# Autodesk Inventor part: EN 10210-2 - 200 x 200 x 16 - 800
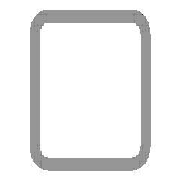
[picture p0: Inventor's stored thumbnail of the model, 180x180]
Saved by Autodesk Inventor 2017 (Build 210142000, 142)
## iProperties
IsCustomPart: 1
Created: 2017-11
Part Number: EN 10210-2 - 200 x 200 x 16 - 800
Material: Steel, Mild
Description: Tube
Document SubType Name: Modeling
Standard: DIN
Designer: iusti
Standard Revision: 2006-07
Standards Organization: DIN
Language: en-US
Size Designation: 200 x 200 x 16
Categories: <MemberInstance><Categories><Category DisplayName="Structural Shapes" InternalName="089c4875-fa83-4c05-b084-43b9cc11f5ed" Mnemonic="GRDR"><CategoryParameter Dis
Stock Number: 200 x 200 x 16
Density: 7.85 g/cm^3
Appearance: Semi-Polished
Mass: 72228.2 g
Surface Area: 11456.6 cm^2
Volume: 9201.05 cm^3
_CCFamilyMember: 94
_CCFamilyDisplayName: DIN EN 10210-2 (Square) - Tube — Sizes in parentheses have been withdrawn
_FrameMemberDoc: Frame Member File
_Version: 15.0.0
_GetPNFromCC: 1
G_L: 800.000 mm
G_W: 200.000 mm
G_H: 200.000 mm
+E8E52DC3-696E-4D1F-9B18-A30D357A272B+CUTDETAIL1: Cut
+4C075105-3F5C-41BE-BEAB-D27544A0B937+CUTDETAIL2: Cut
Author: iusti
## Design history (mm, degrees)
node "Start plane"
node "End plane"
sketch "Sketch"
  geometry: L1 (-100, -76)-(-100, 76); L2 (-76, 100)-(76, 100); L3 (100, 76)-(100, -76); L4 (76, -100)-(-76, -100); L5 (-68, 84)-(68, 84); L6 (84, 68)-(84, -68); L7 (68, -84)-(-68, -84); L8 (-84, -68)-(-84, 68); L9 (0, 146.959)-(0, -146.959) reference; L10 (-146.959, 0)-(146.959, 0) reference; A1 r 24 centre (-76, -76) between (-100, -76) and (-76, -100); A2 r 24 centre (-76, 76) between (-76, 100) and (-100, 76); A3 r 24 centre (76, 76) between (100, 76) and (76, 100); A4 r 24 centre (76, -76) between (76, -100) and (100, -76); A5 r 16 centre (-68, -68) between (-84, -68) and (-68, -84); A6 r 16 centre (-68, 68) between (-68, 84) and (-84, 68); A7 r 16 centre (68, 68) between (84, 68) and (68, 84); A8 r 16 centre (68, -68) between (68, -84) and (84, -68)
  constraints: 16 end point, 16 point on circle, 16 tangent, 8 centre point, 6 equal radius, 4 parallel, 2 perpendicular, 2 other
  dimensions: "d7" = 24 radius of A1 (= G_IR); "d10" = 200 distance between parallel lines of L2 L4 (= G_H); "d11" = 200 distance between parallel lines of L1 L3 (= G_W); "d12" = 16 distance between parallel lines of L3 L6 (= G_T); "d15" = 100 distance between parallel lines of L2 L10 (= 0.5 x d10); "d16" = 100 distance between parallel lines of L9 L3 (= 0.5 x d11); "d19" = 16 radius of A5 (= G_T); "d20" = 16 distance between parallel lines of L4 L7 (= G_T)
extrude "Body" new body sketch "Sketch" stored distance "d3" = 800 (= G_L); taper "d4" = 0 deg
node "Driven Length"
  sketch "Sketch3"
    geometry: L1 (0, 0)-(10, 0) reference
    constraints: 2 end point, 1 horizontal
  workplane "Work Plane3"
  sketch "Sketch4"
    geometry: L1 (-2, 100)-(12, 100) reference; L2 (-2, 900)-(12, 900) reference
    dimensions: "d18" = 800 distance between parallel lines of L1 L2 (derived)
workplane "Work Plane4"
split "Split1"
workplane "Work Plane5"
split "Split2"
body "Solid1"
other parameters: "G_W" = 200 [user parameter; used in 1 equation term], "G_H" = 200 [user parameter; used in 1 equation term], "G_T" = 16 [user parameter; used in 3 equation terms], "G_IR" = 24 [user parameter; used in 1 equation term], "G_L" = 800 (= d18) [user parameter; used in 1 equation term], "G_OFFSET_END" = -135.90437 [user parameter; used in 1 equation term], "B_L" = 1035.90437 [user parameter; used in 1 equation term], "d17" = 90 deg
